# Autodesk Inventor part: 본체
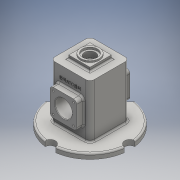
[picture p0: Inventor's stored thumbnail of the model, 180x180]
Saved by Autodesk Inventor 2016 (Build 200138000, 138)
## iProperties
Created: 2018-07
Part Number: 본체
Material: Generic
Document SubType Name: Modeling
Designer: 2-PC11
Density: 1 g/cm^3
Appearance: Default
d4: 360.00 deg
Author: 2-PC11
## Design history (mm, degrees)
sketch "스케치1"
  geometry: A1 r 10 centre (-75, 0) between (-74.333, -9.978) and (-74.333, 9.978); A2 r 10 centre (0, -75) between (9.978, -74.333) and (-9.978, -74.333); A3 r 10 centre (75, 0) between (74.333, 9.978) and (74.333, -9.978); A4 r 10 centre (0, 75) between (-9.978, 74.333) and (9.978, 74.333); A5 r 75 centre (0, 0) between (-74.333, -9.978) and (-9.978, -74.333); A6 r 75 centre (0, 0) between (-9.978, 74.333) and (-74.333, 9.978); A7 r 75 centre (0, 0) between (9.978, -74.333) and (74.333, -9.978); A8 r 75 centre (0, 0) between (74.333, 9.978) and (9.978, 74.333); 1 further point
  constraints: 16 point on circle, 8 centre point, 2 horizontal alignment, 2 vertical alignment, 1 coincident, 17 other
  dimensions: "d1" = 20 diameter of A1; "d4" = 360 deg dimension on point (0, 0) A1.centre (derived); "d6" = 75 radius of A5
extrude "돌출1" new body sketch "스케치1" distance "d7" = 10; taper "d8" = 0 deg
sketch "스케치2"
  geometry: L1 (37, -37)-(-37, -37); L2 (-37, -37)-(-37, 37); L3 (-37, 37)-(37, 37); L4 (37, 37)-(37, -37); L5 (37, -37)-(-37, 37); L6 (-37, -37)-(37, 37); 1 further point
  constraints: 12 end point, 2 midpoint, 2 parallel, 1 horizontal, 1 perpendicular
  dimensions: "d9" = 74 distance of L2.end L3.end; "d10" = 74 distance of L1.end L2.end
extrude "돌출2" join sketch "스케치2" distance "d11" = 100; taper "d12" = 0 deg
node "작업 평면1"
sketch "스케치4"
  geometry: C1 r 17.5 at (0, 0); 1 further point
  constraints: 1 centre point, 1 coincident
  dimensions: "d14" = 35 diameter of C1
extrude "돌출3" join sketch "스케치4" distance "d17" = 3; taper "d18" = 0 deg
sketch "스케치5"
  geometry: L1 (20, -20)-(-20, -20); L2 (-20, -20)-(-20, 20); L3 (-20, 20)-(20, 20); L4 (20, 20)-(20, -20); L5 (20, -20)-(-20, 20); L6 (-20, -20)-(20, 20); 1 further point
  constraints: 12 end point, 2 midpoint, 2 parallel, 1 horizontal, 1 perpendicular
  dimensions: "d19" = 40 distance of L2.end L3.end; "d20" = 40 distance of L1.end L2.end
extrude "돌출4" join sketch "스케치5" stored distance "d21" = 3; taper "d22" = 0 deg
sketch "스케치6"
  geometry: L1 (32, -32)-(-32, -32); L2 (-32, -32)-(-32, 32); L3 (-32, 32)-(32, 32); L4 (32, 32)-(32, -32); L5 (32, -32)-(-32, 32); L6 (-32, -32)-(32, 32); 1 further point
  constraints: 12 end point, 2 midpoint, 2 parallel, 1 horizontal, 1 perpendicular
  dimensions: "d23" = 64 distance of L2.end L3.end; "d24" = 64 distance of L1.end L2.end
sketch "스케치7"
  geometry: L1 (0, 0)-(0, 100) reference; L2 (74, 0)-(0, 0) reference; L3 (74, 0)-(74, 100) reference; L4 (0, 100)-(74, 100) reference; L5 (0, 0)-(0, 100) reference; L6 (27.022, -10)-(46.978, -10) reference; L7 (12, 20)-(62, 20); L8 (62, 20)-(62, 70); L9 (62, 70)-(12, 70); L10 (12, 70)-(12, 20); L11 (12, 20)-(62, 70); L12 (62, 20)-(12, 70); 4 further points
  constraints: 12 end point, 3 midpoint, 2 parallel, 1 horizontal, 1 perpendicular, 1 vertical alignment
  dimensions: "d54" = 50 distance of L9.end L8.end; "d55" = 50 distance of L8.end L7.end; "d56" = 55 distance of point (37, -10) point (37, 45)
  node "투영된 루프1"
extrude "돌출5" cut sketch "스케치6" distance "d27" = 105; taper "d28" = 0 deg
sketch "스케치8"
  geometry: C1 r 14 at (0, 0); 1 further point
  constraints: 1 centre point, 1 coincident
  dimensions: "d33" = 28 diameter of C1
extrude "돌출7" cut sketch "스케치8" distance "d34" = 4; taper "d35" = 0 deg
hole "구멍1" diameter "d38" = 21; stored, may be unused: countersink angle "d42" = 90 deg, drill point angle "d44" = 118 deg; dims "d36" = 10, "d37" = 10, "d39" = 6, "d40" = 4, "d41" = 2, "d43" = 8
extrude "돌출8" join sketch "스케치7" distance "d57" = 13; taper "d59" = 0 deg; dims "d58" = 12, "d60" = 0
hole "구멍3" diameter "d63" = 32; stored, may be unused: countersink angle "d67" = 90 deg, drill point angle "d69" = 118 deg; dims "d61" = 25, "d62" = 25, "d64" = 6, "d65" = 4, "d66" = 2, "d68" = 8
feature "면 기울기1" dims angle "d70" = 10 deg
feature "면 기울기2" dims angle "d71" = 10 deg
feature "면 기울기3" dims angle "d72" = 10 deg
feature "면 기울기4" dims angle "d73" = 10 deg
fillet "모깎기1" dims "d74" = 3
fillet "모깎기2" dims "d75" = 3
fillet "모깎기3" dims "d76" = 3
fillet "모깎기4" dims "d77" = 8
fillet "모깎기5" dims "d78" = 8
fillet "모깎기6" dims "d79" = 3
chamfer "모따기1" distance "d81" = 1; stored, may be unused: second distance "d82" = 2, angle "d83" = 45 deg
chamfer "모따기2" distance "d84" = 1; stored, may be unused: second distance "d85" = 2, angle "d86" = 45 deg
fillet "모깎기8" dims "d87" = 3
fillet "모깎기9" dims "d88" = 6
fillet "모깎기10" dims "d89" = 3
hole "구멍4" diameter "d92" = 3.242; stored, may be unused: countersink angle "d96" = 90 deg, drill point angle "d98" = 118 deg; dims "d90" = 10, "d91" = 10, "d93" = 8, "d94" = 4, "d95" = 2, "d97" = 10
sketch "스케치14" dims "d1" = 20
  geometry: L1 (8.358, -16.998)-(49.642, -16.998); L2 (49.642, -16.998)-(49.642, -23.002); L3 (49.642, -23.002)-(8.358, -23.002); L4 (8.358, -23.002)-(8.358, -16.998); L5 (8.358, -20)-(49.642, -20); L6 (29, -16.998)-(29, -23.002); L7 (11.5, 10)-(46.5, 10) reference; L8 (66, -97)-(66, 0) reference; 1 further point
  constraints: 4 end point, 4 midpoint, 1 horizontal alignment, 1 vertical alignment, 2 other
  dimensions: "d102" = 30 distance from line of L7 L5.end; "d103" = 37 distance from line of L8 L6.start
feature "엠보싱1" sketch "스케치14" dims "d1" = 20, angle "d4" = 360 deg (derived), "d6" = 75, "d104" = 0.5, "d105" = 0
node "솔리드1"
mirror "대칭2"
pattern_circular "원형 패턴1" dims angle "d100" = 360 deg
mirror "대칭3"
